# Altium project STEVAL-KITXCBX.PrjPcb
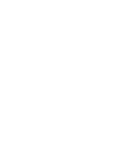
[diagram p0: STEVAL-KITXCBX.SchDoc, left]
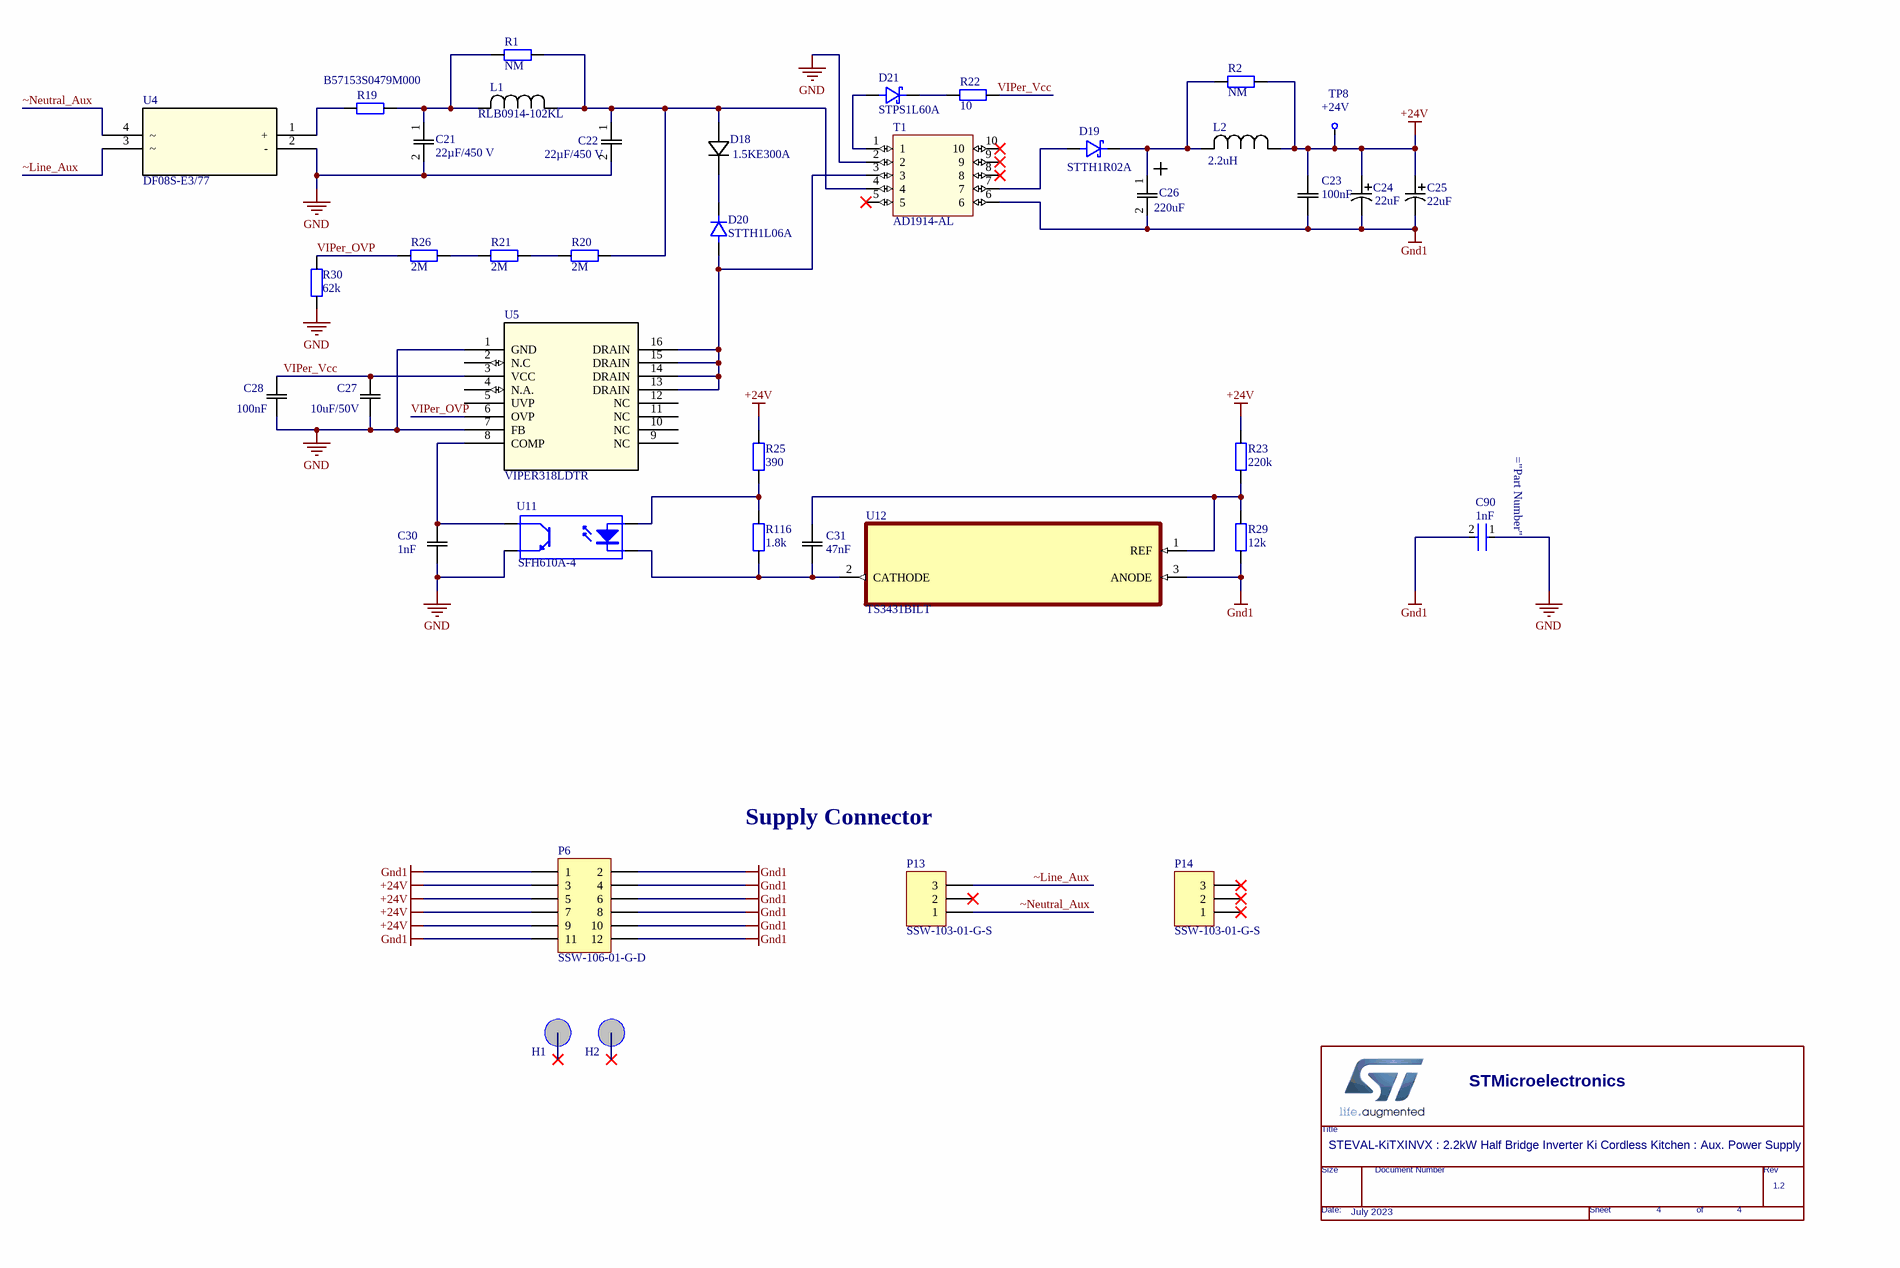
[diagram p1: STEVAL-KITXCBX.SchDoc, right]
1 sheet, 41 parts. Net scope: global (net labels, ports and power ports of the same name join across sheets).
Board file: STEVAL-KITXCBX.PcbDoc

## Sheet STEVAL-KITXCBX.SchDoc
size A3; SheetNumber: 4; SheetTotal: 4

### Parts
*?  Page Create Date: July 2023  RevCode: 1.2  Title: STEVAL-KiTXINVX : 2.2kW Half Bridge Inverter Ki Cordless Kitchen : Aux. Power Supply  Page Number: 4  (hidden comment: ST_Standard_TitleBlock)  (graphical)
C21  22µF/450 V  [CAP_BX_12P5x20_RUB]
C22  22µF/450 V  [CAP_BX_12P5x20_RUB]
C23  100nF  [CAP_0805J_AVX]
C24  22uF  [PCAP_EEHZ_D_PAN]
C25  22uF  [PCAP_EEHZ_D_PAN]
C26  220uF  [CAP_2135_12.5X20_VIS]
C27  10uF/50V  [CAP_X7R_1206_AVX]
C28  100nF  [CAP_0805J_AVX]
C30  1nF  [CAP_0805J_AVX]
C31  47nF  [CAP_0805J_AVX]
C90  1nF  [Vishay_S102K29Y5PN6TJ5R_0]
D18  1.5KE300A  [DO-201_DIO]
D19  STTH1R02A  [DO214AC-SMA]
D20  STTH1L06A  [DO214AC-SMA]
D21  STPS1L60A  [DO214AC-SMA]
H1  Hole  [p-hole-m3]  (value not drawn)  (no BOM)
H2  Hole  [p-hole-m3]  (value not drawn)  (no BOM)
L1  RLB0914-102KL  [IND_RFB0810]
L2  2.2uH  [IND_RFB0810]
P6  SSW-106-01-G-D  [HDR2X6]
P13  SSW-103-01-G-S  [HDR1X3]
P14  SSW-103-01-G-S  [HDR1X3]
R1  NM  [SMD 0805]
R2  NM  [SMD 0805]
R19  B57153S0479M000  [R?]
R20  2M  [RC1206]
R21  2M  [RC1206]
R22  10  [SMD 0805]
R23  220k  [SMD 0805]
R25  390  [SMD 0805]
R26  2M  [RC1206]
R29  12k  [SMD 0805]
R30  62k  [SMD 0805]
R116  1.8k  [SMD 0805]
T1  AD1914-AL  [TDK_B66206B1110T001]
TP8  +24V  [Terminal]
U4  DF08S-E3/77  [SO4_DFS_VIS]
U5  VIPER318LDTR  [SO_18HDTR_STM]
U11  SFH610A-4  [DIP-4]
U12  TS3431BILT  [SOT95P245X112-3N]

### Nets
+24V: C23.2 C24.1 C25.1 L2.1 P6.3 P6.5 P6.7 P6.9 R2.2 R23.2 R25.2 TP8.1(AmpIn)
GND: C21.2 C22.2 C27.1 C28.1 C30.1 C90.1 R30.1 T1.2 U4.2(-) U5.1(GND) U5.7(FB) U11.3(E)
Gnd1: C23.1 C24.2 C25.2 C26.2 C90.2 P6.1 P6.2 P6.4 P6.6 P6.8 P6.10 P6.11 P6.12 R29.1 T1.6 U12.3(ANODE)
VIPer_OVP: R26.1 R30.2 U5.6(OVP)
VIPer_Vcc: C27.2 C28.2 R22.1 U5.3(VCC)
~Line_Aux: P13.3 U4.3
~Neutral_Aux: P13.1 U4.4
NetC21_1: C21.1 L1.2 R1.1 R19.2
NetC22_1: C22.1 D18.2 L1.1 R1.2 R20.2 T1.4
NetC26_1: C26.1 D19.2(Cathode) L2.2 R2.1
NetC30_2: C30.2 U5.8(COMP) U11.4(C)
NetC31_1: C31.1 R116.1 U11.2(K) U12.2(CATHODE)
NetC31_2: C31.2 R23.1 R29.2 U12.1(REF)
NetD18_1: D18.1 D20.2(Cathode)
NetD19_1: D19.1(Anode) T1.7
NetD20_1: D20.1(Anode) T1.3 U5.13(DRAIN) U5.14(DRAIN) U5.15(DRAIN) U5.16(DRAIN)
NetD21_1: D21.1(Anode) T1.1
NetD21_2: D21.2(Cathode) R22.2
NetR19_1: R19.1 U4.1(+)
NetR20_1: R20.1 R21.2
NetR21_1: R21.1 R26.2
NetR25_1: R25.1 R116.2 U11.1(A)

Not connected (* = marked no-connect by the designer): H1 1*; H2 1*; P13 2*; P14 1* 2* 3*; T1 5* 8* 9* 10*; U5 2(N.C) 4(N.A.) 5(UVP) 9(NC) 10(NC) 11(NC) 12(NC)

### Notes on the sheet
- Supply Connector

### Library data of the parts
C21 C22 = 450BXF22M12.5X20: 22 µF 450 V Aluminum Electrolytic Capacitors Radial, Can - 10000 Hrs @ 105°C; Mfr_Name: Rubycon; Manufacturer_Part_Number: EKXN451ELL220MK16S; Type: DEV
C23 C28 C30 C31 = 08051A561JAT2A: No Description Available; Built_By: EMA_UL_Team; Vendor: AVX Corporation; SourceLibrary: AVX_2016-12-14_2; Type: DEV
C24 = EEHZA1H220P: Cap Aluminum 22uF 50V 20% (6.3 X 5.8mm) SMD 0.08 Ohm 1100mA 5000 hr 105°C Embossed T/R; Mfr_Name: Rubycon; Manufacturer_Part_Number: 50PEV22M6.3X6.1; Type: DEV
C25 = EEHZA1H220P: No Description Available; Mfr_Name: Rubycon; Manufacturer_Part_Number: 50PEV22M6.3X6.1; Type: DEV
C26 = MAL213668221E3: No Description Available; Mfr_Name: Vishay; Manufacturer_Part_Number: URZ1J221MHD1TO; Type: DEV
C27 = 12061C104KAT2A: No Description Available; Vendor: AVX Corporation; Built_By: EMA_UL_Team; SourceLibrary: AVX_2012-08-08; Type: DEV
C90 = S102K29Y5PN6TJ5R: Cap Ceramic Single 0.001uF 1000V B 10% (6 X 5mm) Radial Disc 5mm 105°C T/R; Manufacturer 1: TDK; Manufacturer Part Number 1: CK45-B3AD102KYVNA; Voltage Rating: 1kV; Lead/Base Style: Straight
D18 = 1.5KE300A-T: Transient Voltage Suppressor diode, D5.4x7.5, 285.00V .. 315.00V, 1500W; Manufacturer 1: STMicroelectronics
D19 = Diode Schottky STPS1150A: STTH1R02 Series 1.5 A 0.85 V 30 ns Ultrafast Recovery Diode SMT - DO-214AC; Manufacturer 1: STMicroelectronics
D20 = Diode STH1L06A: Diode; Manufacturer 1: STMicroelectronics; Forward Current: 1A; Forward Voltage: 1.3V; Max Surge Current: 20A; Max Reverse Current: 1uA; Recovery Time: 80ns; Max Repetitive Reverse Voltage (Vrrm): 600V; Max Forward Surge Current (Ifsm): 10A; Element Configuration: Single; Polarity: Standard
D21 = Diode STPS1L30A: Small Signal Schottky Diode; Max Surge Current: 75A; Forward Current: 1A; Max Reverse Current: 200uA; Forward Voltage: 395mV; Max Repetitive Reverse Voltage (Vrrm): 30V; Element Configuration: Single; Polarity: Standard
L1 = RFB0810-330L: Inductor Power Wirewound 1mH 10% 252KHz 40Q-Factor Ferrite 300mA 2.1Ohm DCR RDL Bag; Manufacturer 1: Bourns
L2 = RFB0810-330L: Inductor, Fixed, Power, Ferrite Core, 2.2uH, 2.6A, 29mohm; Manufacturer 1: KEMET; Manufacturer Part Number 1: SBCP-47HY2R2B
P6 = Header 6X2: connector, 6-Pin, Dual row
P13 P14 = Header 3: connector, 3-Pin
R1 R2 R20 R21 R26 = RESISTOR: RESISTOR 1206; SMT/THT: SMT
R19 = RESISTOR: Inrush current limiters include PTC and NTC Thermistors.; Manufacturer 1: TDK EPCOS; SMT/THT: SMT
R22 R23 R25 R29 R30 R116 = RESISTOR: RESISTOR 0805; SMT/THT: SMT
T1 = B66206B1110T001: Coil Craft Transformer; Operating_Temp: +155C MAX
TP8 = TESTP: Test Point; SMT/THT: THT
U4 = DF08S-E3/77: Diode Rectifier Bridge Single 800V 1A 4-Pin Case DFS T/R; Mfr_Name: Vishay; Manufacturer 1: Vishay Semiconductors
U5 = VIPER318HDTR: AC to DC Switching Converter Boost/Buck/Flyback 4.25V 145kHz T/R 16-Pin SO N; Manufacturer 1: STMicroelectronics
U11 = Optoisolator1: 4-Pin Phototransistor Optocoupler; P/N: SFH610A-4 - CTR: 3.2
U12 = TS3431BILT: V-Ref Adjustable 1.24V to 24V 100mA 3-Pin SOT-23 T/R / IC VREF SHUNT ADJ SOT23-3; Manufacturer 1: STMicroelectronics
